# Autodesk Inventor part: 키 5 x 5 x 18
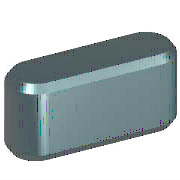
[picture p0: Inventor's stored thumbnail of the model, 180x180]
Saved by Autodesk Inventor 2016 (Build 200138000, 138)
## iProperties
Created: 2012-02
Part Number: 키 5 x 5 x 18
Material: 강철, 연강
Description: 키 및 해당 키홈
Document SubType Name: Modeling
Standard: KS B 1311
Designer: mduedu
Standards Organization: KS
Language: ko-KR
Size Designation: 5 x 5 x 18
Categories: <MemberInstance><Categories><Category DisplayName="샤프트 부품" InternalName="7f7aeb1f-a693-4053-b835-cee3144e0d98" Mnemonic="SHFT"><Category DisplayName="키" Interna
Density: 7.86 g/cm^3
Mass: 3.27476 g
Surface Area: 3.57848 cm^2
Volume: 0.416636 cm^3
Appearance: 노란색
IsCustomPart: 1
Author: mduedu
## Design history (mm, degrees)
workplane "Work Plane1"
workplane "Work Plane2"
sketch "스케치1"
  geometry: L1 (2.5, 2.5)-(15.5, 2.5); L2 (15.5, -2.5)-(2.5, -2.5); L3 (0, 9.4)-(0, -7.4) reference; L4 (-5, 0)-(30, 0) reference; L5 (18, 0)-(18, 7); A1 r 2.5 centre (2.5, 0) between (2.5, 2.5) and (2.5, -2.5); A2 r 2.5 centre (15.5, 0) between (15.5, -2.5) and (15.5, 2.5)
  constraints: 6 end point, 5 point on circle, 4 tangent, 3 point on line, 2 centre point, 1 horizontal, 1 parallel, 1 perpendicular
  dimensions: "d0" = 2.5 radius of A1 (= 0.5 x PB); "d13" = 2.5 radius of A2 (= 0.5 x PB); "d14" = 18 distance between parallel lines of L5 L3 (= NLG)
extrude "본체1" new body sketch "스케치1" taper "d3" = 0 deg; stored distance "d4" = 10
workplane "Work Plane3"
body "Solid1"
chamfer "모따기1" distance "d8" = 0.4 (= PHH); stored, may be unused: second distance "d9" = 0.4 (= PHH), angle "d15" = 45 deg
other parameters: "d1" = -3 (= -PNT), "d2" = 2 (= PH - PNT), "NLG" = 18 [user parameter; used in 3 equation terms], "PB" = 5 [user parameter; used in 2 equation terms], "PNT" = 3 [user parameter; used in 2 equation terms], "PH" = 5 [user parameter; used in 1 equation term], "PHH" = 0.4 [user parameter; used in 2 equation terms], "d10" = 0, "d16" = 0, "d17" = 0, "d18" = 0, "WDMIN" = 12 [user parameter], "PLB2" = 18 (= NLG) [user parameter], "WDMAX" = 17 [user parameter], "PLB1" = 18 (= NLG) [user parameter], "RR" = 0.16 [user parameter], "PUEB" = 2.3 [user parameter]
